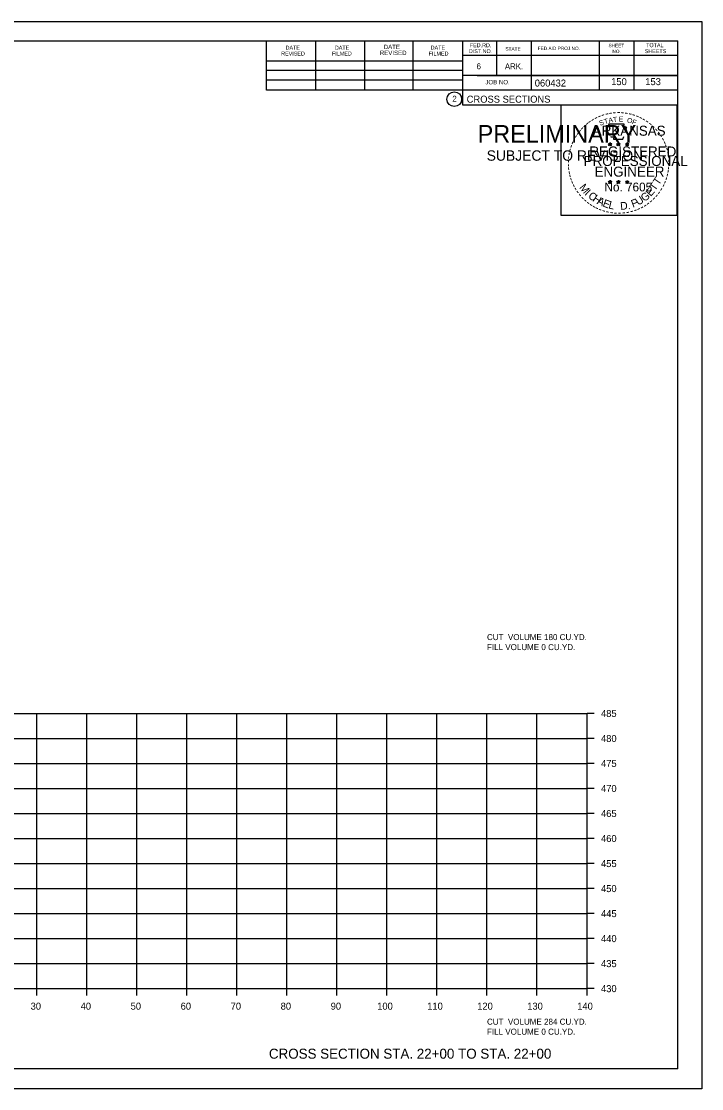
# Model space of a CAD drawing. Extents: x 1538688 to 1540766, y 656250 to 671912.
# Drawn here: x 1539401 to 1539537.1, y 656764.6 to 656977.9 of the extents above; entities that cross this region are included whole.
import ezdxf

# ---------------------------------------------------------------- set-up
doc = ezdxf.new("R2010")
doc.units = 0
for name, color, linetype in [('15', 7, 'Continuous'), ('22', 7, 'Continuous'), ('26', 7, 'Continuous'), ('7', 7, 'Continuous'), ('8', 7, 'Continuous'), ('9', 7, 'Continuous'), ('Borings', 7, 'Continuous'), ('Horizontal Alignment', 7, 'Continuous'), ('RipRap', 7, 'Continuous')]:
    doc.layers.add(name, color=color, linetype=linetype)

msp = doc.modelspace()

# ---------------------------------------------------------------- linework, layer by layer
at = {"layer": '22'}
for p, q in [((1539234.13, 656839.56), (1539514.13, 656839.56)), ((1539404.13, 656784.56), (1539404.13, 656839.56)), ((1539414.13, 656784.56), (1539414.13, 656839.56)), ((1539424.13, 656784.56), (1539424.13, 656839.56)), ((1539434.13, 656784.56), (1539434.13, 656839.56)), ((1539444.13, 656784.56), (1539444.13, 656839.56)), ((1539454.13, 656784.56), (1539454.13, 656839.56)), ((1539464.13, 656784.56), (1539464.13, 656839.56)), ((1539474.13, 656784.56), (1539474.13, 656839.56)), ((1539484.13, 656784.56), (1539484.13, 656839.56)), ((1539494.13, 656784.56), (1539494.13, 656839.56)), ((1539504.13, 656784.56), (1539504.13, 656839.56)), ((1539514.13, 656784.56), (1539514.13, 656839.56)), ((1539234.13, 656834.56), (1539514.13, 656834.56)), ((1539234.13, 656829.56), (1539514.13, 656829.56)), ((1539234.13, 656824.56), (1539514.13, 656824.56)), ((1539234.13, 656819.56), (1539514.13, 656819.56)), ((1539234.13, 656814.56), (1539514.13, 656814.56)), ((1539234.13, 656809.56), (1539514.13, 656809.56)), ((1539234.13, 656804.56), (1539514.13, 656804.56)), ((1539234.13, 656799.56), (1539514.13, 656799.56)), ((1539234.13, 656794.56), (1539514.13, 656794.56)), ((1539234.13, 656789.56), (1539514.13, 656789.56)), ((1539234.13, 656784.56), (1539514.13, 656784.56))]:
    msp.add_line(p, q, dxfattribs=at)
at = {"layer": '26'}
for p, q in [((1539203.73, 656977.91), (1539537.06, 656977.91)), ((1539203.73, 656764.58), (1539537.06, 656764.58))]:
    msp.add_line(p, q, dxfattribs=at)
for points in [[(1539203.72, 656977.91), (1539537.06, 656977.91), (1539537.06, 656764.57), (1539203.72, 656764.57)], [(1539508.98, 656961.25), (1539532.08, 656961.25), (1539532.08, 656939.1), (1539508.98, 656939.1)]]:
    msp.add_lwpolyline(points, close=True, dxfattribs=at)
at = {"layer": '8'}
for p, q in [((1539518.39, 656953.46), (1539518.74, 656953.35)), ((1539518.39, 656953.46), (1539518.64, 656953.42)), ((1539518.39, 656953.46), (1539518.62, 656953.34)), ((1539518.52, 656953.05), (1539518.74, 656953.35)), ((1539518.52, 656953.05), (1539518.65, 656953.3)), ((1539518.52, 656953.05), (1539518.73, 656953.27)), ((1539518.74, 656953.72), (1539518.7, 656953.46)), ((1539518.95, 656953.05), (1539518.73, 656953.27)), ((1539518.74, 656953.35), (1539518.74, 656953.72)), ((1539518.74, 656953.72), (1539518.79, 656953.47)), ((1539519.08, 656953.46), (1539518.74, 656953.35)), ((1539518.95, 656953.05), (1539518.74, 656953.35)), ((1539519.08, 656953.46), (1539518.8, 656953.41)), ((1539518.95, 656953.05), (1539518.81, 656953.35)), ((1539519.08, 656953.46), (1539518.88, 656953.36)), ((1539520.06, 656953.46), (1539520.41, 656953.35)), ((1539520.06, 656953.46), (1539520.31, 656953.42)), ((1539520.06, 656953.46), (1539520.29, 656953.34)), ((1539520.19, 656953.05), (1539520.41, 656953.35)), ((1539520.19, 656953.05), (1539520.32, 656953.3)), ((1539520.19, 656953.05), (1539520.4, 656953.27)), ((1539520.41, 656953.72), (1539520.37, 656953.46)), ((1539520.62, 656953.05), (1539520.4, 656953.27)), ((1539520.41, 656953.35), (1539520.41, 656953.72)), ((1539520.41, 656953.72), (1539520.46, 656953.47)), ((1539520.75, 656953.46), (1539520.41, 656953.35)), ((1539520.62, 656953.05), (1539520.41, 656953.35)), ((1539520.75, 656953.46), (1539520.47, 656953.41)), ((1539520.62, 656953.05), (1539520.48, 656953.35)), ((1539520.75, 656953.46), (1539520.55, 656953.36)), ((1539521.82, 656953.45), (1539522.17, 656953.34)), ((1539521.82, 656953.45), (1539522.07, 656953.41)), ((1539521.82, 656953.45), (1539522.06, 656953.33)), ((1539521.95, 656953.04), (1539522.17, 656953.34)), ((1539521.95, 656953.04), (1539522.08, 656953.29)), ((1539521.95, 656953.04), (1539522.17, 656953.26)), ((1539522.17, 656953.7), (1539522.13, 656953.45)), ((1539522.17, 656953.34), (1539522.17, 656953.7)), ((1539522.17, 656953.7), (1539522.22, 656953.45)), ((1539522.52, 656953.45), (1539522.17, 656953.34)), ((1539522.38, 656953.04), (1539522.17, 656953.34)), ((1539522.38, 656953.04), (1539522.17, 656953.26)), ((1539522.52, 656953.45), (1539522.23, 656953.4)), ((1539522.38, 656953.04), (1539522.25, 656953.33)), ((1539522.52, 656953.45), (1539522.31, 656953.35)), ((1539518.38, 656945.89), (1539518.73, 656945.78)), ((1539518.38, 656945.89), (1539518.64, 656945.84)), ((1539518.38, 656945.89), (1539518.62, 656945.77)), ((1539518.52, 656945.48), (1539518.73, 656945.78)), ((1539518.52, 656945.48), (1539518.64, 656945.73)), ((1539518.52, 656945.48), (1539518.73, 656945.7)), ((1539518.73, 656946.14), (1539518.69, 656945.89)), ((1539518.73, 656945.78), (1539518.73, 656946.14)), ((1539518.73, 656946.14), (1539518.78, 656945.89)), ((1539519.08, 656945.89), (1539518.73, 656945.78)), ((1539518.95, 656945.48), (1539518.73, 656945.78)), ((1539518.95, 656945.48), (1539518.73, 656945.7)), ((1539519.08, 656945.89), (1539518.79, 656945.84)), ((1539518.95, 656945.48), (1539518.81, 656945.77)), ((1539519.08, 656945.89), (1539518.88, 656945.79)), ((1539520.05, 656945.89), (1539520.4, 656945.78)), ((1539520.05, 656945.89), (1539520.31, 656945.84)), ((1539520.05, 656945.89), (1539520.29, 656945.77)), ((1539520.19, 656945.48), (1539520.4, 656945.78)), ((1539520.19, 656945.48), (1539520.31, 656945.73)), ((1539520.19, 656945.48), (1539520.4, 656945.7)), ((1539520.4, 656946.14), (1539520.36, 656945.89)), ((1539520.4, 656945.78), (1539520.4, 656946.14)), ((1539520.4, 656946.14), (1539520.45, 656945.89)), ((1539520.75, 656945.89), (1539520.4, 656945.78)), ((1539520.61, 656945.48), (1539520.4, 656945.78)), ((1539520.61, 656945.48), (1539520.4, 656945.7)), ((1539520.75, 656945.89), (1539520.46, 656945.84)), ((1539520.61, 656945.48), (1539520.48, 656945.77)), ((1539520.75, 656945.89), (1539520.54, 656945.79)), ((1539521.82, 656945.88), (1539522.17, 656945.77)), ((1539521.82, 656945.88), (1539522.07, 656945.83)), ((1539521.82, 656945.88), (1539522.06, 656945.76)), ((1539521.95, 656945.47), (1539522.17, 656945.77)), ((1539521.95, 656945.47), (1539522.08, 656945.72)), ((1539521.95, 656945.47), (1539522.17, 656945.69)), ((1539522.17, 656946.13), (1539522.13, 656945.88)), ((1539522.17, 656945.77), (1539522.17, 656946.13)), ((1539522.17, 656946.13), (1539522.22, 656945.88)), ((1539522.52, 656945.88), (1539522.17, 656945.77)), ((1539522.38, 656945.47), (1539522.17, 656945.77)), ((1539522.38, 656945.47), (1539522.17, 656945.69)), ((1539522.52, 656945.88), (1539522.23, 656945.83)), ((1539522.38, 656945.47), (1539522.24, 656945.76)), ((1539522.52, 656945.88), (1539522.31, 656945.78))]:
    msp.add_line(p, q, dxfattribs=at)
for points in [[(1539518.43, 656957.34), (1539518.7, 656956.51)], [(1539521.94, 656956.42), (1539522.08, 656956.7), (1539521.4, 656956.68), (1539521.54, 656957.34), (1539518.43, 656957.34)], [(1539518.92, 656954.92), (1539518.92, 656954.83), (1539519.48, 656954.81), (1539519.43, 656954.34), (1539521.3, 656954.34), (1539521.5, 656954.87)], [(1539518.74, 656953.72), (1539518.95, 656953.05), (1539518.39, 656953.46), (1539519.08, 656953.46), (1539518.52, 656953.05), (1539518.74, 656953.72)], [(1539520.41, 656953.72), (1539520.62, 656953.05), (1539520.06, 656953.46), (1539520.75, 656953.46), (1539520.19, 656953.05), (1539520.41, 656953.72)], [(1539522.17, 656953.7), (1539522.38, 656953.04), (1539521.82, 656953.45), (1539522.52, 656953.45), (1539521.95, 656953.04), (1539522.17, 656953.7)], [(1539518.73, 656946.14), (1539518.95, 656945.48), (1539518.38, 656945.89), (1539519.08, 656945.89), (1539518.52, 656945.48), (1539518.73, 656946.14)], [(1539520.4, 656946.14), (1539520.61, 656945.48), (1539520.05, 656945.89), (1539520.75, 656945.89), (1539520.19, 656945.48), (1539520.4, 656946.14)], [(1539522.17, 656946.13), (1539522.38, 656945.47), (1539521.82, 656945.88), (1539522.52, 656945.88), (1539521.95, 656945.47), (1539522.17, 656946.13)]]:
    msp.add_lwpolyline(points, dxfattribs=at)
for centre, radius in [((1539518.74, 656953.35), 0.172), ((1539518.74, 656953.35), 0.145), ((1539518.74, 656953.35), 0.116), ((1539518.74, 656953.35), 0.0991), ((1539518.74, 656953.35), 0.0747), ((1539518.74, 656953.35), 0.0495), ((1539518.74, 656953.35), 0.0296), ((1539520.41, 656953.35), 0.172), ((1539520.41, 656953.35), 0.145), ((1539520.41, 656953.35), 0.116), ((1539520.41, 656953.35), 0.0991), ((1539520.41, 656953.35), 0.0747), ((1539520.41, 656953.35), 0.0495), ((1539520.41, 656953.35), 0.0296), ((1539522.17, 656953.34), 0.172), ((1539522.17, 656953.34), 0.145), ((1539522.17, 656953.34), 0.116), ((1539522.17, 656953.34), 0.0991), ((1539522.17, 656953.34), 0.0747), ((1539522.17, 656953.34), 0.0495), ((1539522.17, 656953.34), 0.0296), ((1539518.73, 656945.78), 0.172), ((1539518.73, 656945.78), 0.145), ((1539518.73, 656945.78), 0.116), ((1539518.73, 656945.78), 0.0991), ((1539518.73, 656945.78), 0.0747), ((1539518.73, 656945.78), 0.0495), ((1539518.73, 656945.78), 0.0296), ((1539520.4, 656945.78), 0.172), ((1539520.4, 656945.78), 0.145), ((1539520.4, 656945.78), 0.116), ((1539520.4, 656945.78), 0.0991), ((1539520.4, 656945.78), 0.0747), ((1539520.4, 656945.78), 0.0495), ((1539520.4, 656945.78), 0.0296), ((1539522.17, 656945.77), 0.172), ((1539522.17, 656945.77), 0.145), ((1539522.17, 656945.77), 0.116), ((1539522.17, 656945.77), 0.0991), ((1539522.17, 656945.77), 0.0747), ((1539522.17, 656945.77), 0.0495), ((1539522.17, 656945.77), 0.0296)]:
    msp.add_circle(centre, radius, dxfattribs=at)
at = {"layer": 'Borings'}
for p, q in [((1539514.13, 656784.56), (1539514.13, 656839.56)), ((1539515.53, 656839.56), (1539514.13, 656839.56)), ((1539515.53, 656834.56), (1539514.13, 656834.56)), ((1539515.53, 656829.56), (1539514.13, 656829.56)), ((1539515.53, 656824.56), (1539514.13, 656824.56)), ((1539515.53, 656819.56), (1539514.13, 656819.56)), ((1539515.53, 656814.56), (1539514.13, 656814.56)), ((1539515.53, 656809.56), (1539514.13, 656809.56)), ((1539515.53, 656804.56), (1539514.13, 656804.56)), ((1539515.53, 656799.56), (1539514.13, 656799.56)), ((1539515.53, 656794.56), (1539514.13, 656794.56)), ((1539515.53, 656789.56), (1539514.13, 656789.56)), ((1539234.13, 656784.56), (1539514.13, 656784.56)), ((1539404.13, 656783.16), (1539404.13, 656784.56)), ((1539414.13, 656783.16), (1539414.13, 656784.56)), ((1539424.13, 656783.16), (1539424.13, 656784.56)), ((1539434.13, 656783.16), (1539434.13, 656784.56)), ((1539444.13, 656783.16), (1539444.13, 656784.56)), ((1539454.13, 656783.16), (1539454.13, 656784.56)), ((1539464.13, 656783.16), (1539464.13, 656784.56)), ((1539474.13, 656783.16), (1539474.13, 656784.56)), ((1539484.13, 656783.16), (1539484.13, 656784.56)), ((1539494.13, 656783.16), (1539494.13, 656784.56)), ((1539504.13, 656783.16), (1539504.13, 656784.56)), ((1539514.13, 656783.16), (1539514.13, 656784.56)), ((1539515.53, 656784.56), (1539514.13, 656784.56))]:
    msp.add_line(p, q, dxfattribs=at)
at = {"layer": 'RipRap'}
for p, q in [((1539216.13, 656974.02), (1539532.31, 656974.02)), ((1539450.05, 656964.14), (1539450.05, 656974.02)), ((1539459.91, 656964.14), (1539459.91, 656973.82)), ((1539469.67, 656964.14), (1539469.67, 656973.82)), ((1539479.35, 656964.14), (1539479.35, 656973.82)), ((1539489.21, 656974.02), (1539489.21, 656961.22)), ((1539496.05, 656974.02), (1539496.05, 656967.08)), ((1539502.99, 656974.02), (1539502.99, 656964.14)), ((1539516.57, 656974.02), (1539516.57, 656964.14)), ((1539523.51, 656974.02), (1539523.51, 656964.14)), ((1539532.31, 656768.56), (1539532.31, 656974.02)), ((1539532.31, 656971.08), (1539489.21, 656971.08)), ((1539532.31, 656971.1), (1539532.31, 656971.1)), ((1539450.05, 656970), (1539489.21, 656970)), ((1539450.05, 656968.14), (1539489.21, 656968.14)), ((1539532.31, 656967.08), (1539489.21, 656967.08)), ((1539492.17, 656967.08), (1539532.31, 656967.08)), ((1539450.05, 656964.14), (1539450.05, 656966.2)), ((1539450.05, 656966.2), (1539489.21, 656966.2)), ((1539532.31, 656964.14), (1539450.05, 656964.14)), ((1539489.21, 656961.22), (1539532.31, 656961.22)), ((1539532.31, 656768.56), (1539216.13, 656768.56))]:
    msp.add_line(p, q, dxfattribs=at)
msp.add_circle((1539487.59, 656962.35), 1.47, dxfattribs=at)

# ---------------------------------------------------------------- texts
at = {"layer": '15'}
msp.add_text('CROSS SECTION STA. 22+00 TO STA. 22+00', height=2, dxfattribs=at).set_placement((1539450.52, 656770.56))
at = {"layer": '7'}
for s, p in [('150', (1539518.96, 656965.16)), ('153', (1539525.78, 656965.16))]:
    msp.add_text(s, height=1.4, dxfattribs=at).set_placement(p)
at = {"layer": '8'}
for s, height, rotation, p in [('-', 1.6, 34.0636, (1539515.31, 656957.51)), ('-', 1.6, 28.7918, (1539515.91, 656957.88)), ('-', 1.6, 24.3072, (1539516.54, 656958.2)), ('-', 1.6, 19.1761, (1539517.18, 656958.47)), ('T', 1, 16.4036, (1539517.7, 656957.35)), ('-', 1.6, 13.6301, (1539517.93, 656958.71)), ('A', 1, 11.2132, (1539518.52, 656957.6)), ('-', 1.6, 10.2193, (1539518.6, 656958.87)), ('T', 1, 6.0228, (1539519.37, 656957.77)), ('-', 1.6, 5.8968, (1539519.33, 656958.98)), ('-', 1.6, 0.1862, (1539520.11, 656959.05)), ('E', 1, 0.8323, (1539520.48, 656957.88)), ('-', 1.6, 357.743, (1539520.83, 656959.04)), ('-', 1.6, 352.1617, (1539521.57, 656958.98)), ('O', 1, 350.4515, (1539522.08, 656957.67)), ('-', 1.6, 347.2049, (1539522.29, 656958.87)), ('F', 1, 340.0707, (1539523.04, 656957.44)), ('-', 1.6, 342.3362, (1539522.93, 656958.71)), ('-', 1.6, 337.8551, (1539523.66, 656958.49)), ('-', 1.6, 334.1211, (1539524.29, 656958.22)), ('-', 1.6, 329.6409, (1539524.87, 656957.94)), ('-', 1.6, 50.6142, (1539512.97, 656955.36)), ('-', 1.6, 48.423, (1539513.38, 656955.84)), ('-', 1.6, 42.9622, (1539513.83, 656956.32)), ('-', 1.6, 38.9507, (1539514.26, 656956.74)), ('-', 1.6, 36.2317, (1539514.73, 656957.12)), ('ARKANSAS', 2, 360, (1539515.28, 656955.05)), ('S', 1, 21.594, (1539516.78, 656957.02)), ('-', 1.6, 325.8627, (1539525.51, 656957.58)), ('-', 1.6, 320.5297, (1539526.12, 656957.15)), ('-', 1.6, 315.5786, (1539526.72, 656956.66)), ('-', 1.6, 309.8797, (1539527.29, 656956.11)), ('-', 1.6, 62.8713, (1539511.92, 656953.65)), ('-', 1.6, 58.0706, (1539512.24, 656954.26)), ('-', 1.6, 54.2325, (1539512.56, 656954.79)), ('-', 1.6, 306.6522, (1539527.82, 656955.51)), ('-', 1.4, 303.6753, (1539528.3, 656954.94)), ('-', 1.6, 299.6684, (1539528.62, 656954.34)), ('-', 1.6, 75.461, (1539511.25, 656951.69)), ('-', 1.6, 72.3945, (1539511.45, 656952.41)), ('-', 1.6, 67.7743, (1539511.66, 656953.04)), ('REGISTERED', 2, 360, (1539514.6, 656950.9)), ('DWB', 0.01, 360, (1539518.72, 656953.35)), ('DWB', 0.01, 360, (1539520.39, 656953.35)), ('DWB', 0.01, 360, (1539522.16, 656953.33)), ('-', 1.6, 294.6628, (1539528.95, 656953.72)), ('-', 1.6, 290.5728, (1539529.2, 656953.15)), ('-', 1.6, 285.1233, (1539529.44, 656952.57)), ('-', 1.6, 280.5493, (1539529.64, 656951.82)), ('-', 1.6, 89.0622, (1539511.02, 656949.59)), ('-', 1.6, 85.1863, (1539511.04, 656950.29)), ('-', 1.6, 81.2013, (1539511.12, 656950.98)), ('PROFESSIONAL', 2, 360, (1539513.46, 656949)), ('-', 1.6, 276.5962, (1539529.8, 656951.06)), ('-', 1.6, 274.3301, (1539529.86, 656950.33)), ('-', 1.6, 94.1959, (1539511.05, 656948.86)), ('-', 1.6, 98.9479, (1539511.12, 656948.2)), ('-', 1.6, 101.7149, (1539511.26, 656947.46)), ('ENGINEER', 2, 360, (1539515.64, 656946.87)), ('-', 1.6, 260.9953, (1539529.8, 656948.38)), ('-', 1.6, 263.5172, (1539529.87, 656949.04)), ('-', 1.6, 269.9407, (1539529.89, 656949.7)), ('-', 1.6, 105.4578, (1539511.42, 656946.87)), ('-', 1.6, 109.0874, (1539511.63, 656946.24)), ('-', 1.6, 114.0643, (1539511.89, 656945.64)), ('M', 1.54, 308.9175, (1539512.5, 656944.67)), ('No. 7605', 1.757, 360, (1539517.62, 656943.92)), ('DWB', 0.01, 360, (1539518.72, 656945.77)), ('DWB', 0.01, 360, (1539520.39, 656945.77)), ('DWB', 0.01, 360, (1539522.15, 656945.76)), ('T', 1.54, 55.055, (1539527.72, 656943.92)), ('T', 1.54, 55.055, (1539528.45, 656945.04)), ('-', 1.6, 247.8887, (1539529.29, 656946.31)), ('-', 1.6, 252.8681, (1539529.51, 656946.98)), ('-', 1.6, 255.7626, (1539529.69, 656947.7)), ('-', 1.6, 115.7289, (1539512.19, 656945.02)), ('-', 1.6, 120.4471, (1539512.55, 656944.44)), ('-', 1.6, 125.8934, (1539512.95, 656943.88)), ('-', 1.6, 130.7181, (1539513.42, 656943.33)), ('I', 1.54, 316.4636, (1539513.55, 656943.35)), ('C', 1.54, 324.0197, (1539514.22, 656942.73)), ('H', 1.54, 327.5342, (1539515.13, 656942.07)), ('G', 1.54, 38.2173, (1539525.62, 656941.78)), ('E', 1.54, 48.7313, (1539526.87, 656942.8)), ('-', 1.6, 231.2538, (1539527.8, 656943.71)), ('-', 1.6, 233.8452, (1539528.23, 656944.28)), ('-', 1.6, 239.0712, (1539528.63, 656944.93)), ('-', 1.6, 244.6197, (1539529.03, 656945.68)), ('-', 1.6, 134.2238, (1539513.93, 656942.78)), ('-', 1.6, 138.9338, (1539514.46, 656942.32)), ('-', 1.6, 144.6463, (1539515.01, 656941.91)), ('-', 1.6, 148.0898, (1539515.57, 656941.54)), ('A', 1.54, 332.5513, (1539515.98, 656941.53)), ('E', 1.54, 339.2068, (1539517.14, 656940.97)), ('L', 1.54, 346.2929, (1539518.33, 656940.55)), ('D.', 1.54, 5.2602, (1539520.84, 656940.21)), ('F', 1.54, 20.8202, (1539523.29, 656940.65)), ('U', 1.54, 34.4052, (1539524.42, 656941.04)), ('-', 1.6, 212.2491, (1539525.72, 656941.78)), ('-', 1.6, 215.7363, (1539526.25, 656942.17)), ('-', 1.6, 221.0851, (1539526.8, 656942.64)), ('-', 1.6, 225.7653, (1539527.32, 656943.15)), ('-', 1.6, 151.5704, (1539516.15, 656941.21)), ('-', 1.6, 154.6002, (1539516.68, 656940.97)), ('-', 1.6, 158.5612, (1539517.3, 656940.71)), ('-', 1.6, 162.7983, (1539517.99, 656940.5)), ('-', 1.6, 167.5555, (1539518.7, 656940.34)), ('-', 1.6, 173.1155, (1539519.47, 656940.23)), ('-', 1.6, 176.5183, (1539520.22, 656940.17)), ('-', 1.6, 181.5918, (1539520.97, 656940.19)), ('-', 1.6, 185.8167, (1539521.77, 656940.27)), ('-', 1.6, 191.2858, (1539522.51, 656940.4)), ('-', 1.6, 195.4743, (1539523.24, 656940.6)), ('-', 1.6, 200.7184, (1539523.92, 656940.84)), ('-', 1.6, 204.2516, (1539524.54, 656941.11)), ('-', 1.6, 207.3568, (1539525.16, 656941.43))]:
    msp.add_text(s, height=height, rotation=rotation, dxfattribs=at).set_placement(p)
at = {"layer": '9'}
for s, height, p in [('PRELIMINARY', 3.5, (1539492.26, 656953.68)), ('DWB', 0.01, (1539493, 656955.53)), ('SUBJECT TO REVISION', 2.0751, (1539494.07, 656950.05))]:
    msp.add_text(s, height=height, rotation=360, dxfattribs=at).set_placement(p)
at = {"layer": 'Horizontal Alignment'}
for s, height, p in [('CUT  VOLUME 180 CU.YD.', 1.2, (1539494.13, 656854.23)), ('FILL VOLUME 0 CU.YD.', 1.2, (1539494.13, 656852.23)), ('485', 1.4, (1539516.93, 656838.86)), ('480', 1.4, (1539516.93, 656833.86)), ('475', 1.4, (1539516.93, 656828.86)), ('470', 1.4, (1539516.93, 656823.86)), ('465', 1.4, (1539516.93, 656818.86)), ('460', 1.4, (1539516.93, 656813.86)), ('455', 1.4, (1539516.93, 656808.86)), ('450', 1.4, (1539516.93, 656803.86)), ('445', 1.4, (1539516.93, 656798.86)), ('440', 1.4, (1539516.93, 656793.86)), ('435', 1.4, (1539516.93, 656788.86)), ('430', 1.4, (1539516.93, 656783.86)), ('30', 1.4, (1539402.87, 656780.36)), ('40', 1.4, (1539412.87, 656780.36)), ('50', 1.4, (1539422.87, 656780.36)), ('60', 1.4, (1539432.87, 656780.36)), ('70', 1.4, (1539442.87, 656780.36)), ('80', 1.4, (1539452.87, 656780.36)), ('90', 1.4, (1539462.87, 656780.36)), ('100', 1.4, (1539472.17, 656780.36)), ('110', 1.4, (1539482.17, 656780.36)), ('120', 1.4, (1539492.17, 656780.36)), ('130', 1.4, (1539502.17, 656780.36)), ('140', 1.4, (1539512.17, 656780.36)), ('CUT  VOLUME 284 CU.YD.', 1.2, (1539494.13, 656777.36)), ('FILL VOLUME 0 CU.YD.', 1.2, (1539494.13, 656775.36))]:
    msp.add_text(s, height=height, dxfattribs=at).set_placement(p)
at = {"layer": 'RipRap'}
for s, height, p in [('DATE', 0.879, (1539473.49, 656972.36)), ('FED.RD.', 0.782, (1539490.69, 656972.74)), ('SHEET', 0.684, (1539518.43, 656972.74)), ('TOTAL', 0.782, (1539525.95, 656972.74)), ('REVISED', 0.782, (1539452.97, 656971.08)), ('DATE', 0.782, (1539453.85, 656972.26)), ('FILMED', 0.782, (1539463.13, 656971.08)), ('DATE', 0.782, (1539463.71, 656972.26)), ('REVISED', 0.879, (1539472.71, 656971.18)), ('FILMED', 0.782, (1539482.47, 656971.08)), ('DATE', 0.782, (1539482.87, 656972.26)), ('DIST.NO.', 0.782, (1539490.49, 656971.56)), ('STATE', 0.684, (1539497.81, 656972.06)), ('FED.AID PROJ.NO.', 0.684, (1539504.27, 656972.16)), ('NO.', 0.684, (1539519.21, 656971.56)), ('SHEETS', 0.782, (1539525.67, 656971.56)), ('6', 1.17, (1539492.05, 656968.34)), ('ARK.', 1.172, (1539497.71, 656968.34)), ('JOB NO.', 0.879, (1539493.81, 656965.32)), ('060432', 1.4, (1539503.68, 656964.88)), ('2', 1.17, (1539487.21, 656961.87)), ('CROSS SECTIONS', 1.4, (1539490.07, 656961.65))]:
    msp.add_text(s, height=height, rotation=360, dxfattribs=at).set_placement(p)

doc.saveas('drawing.dxf')
